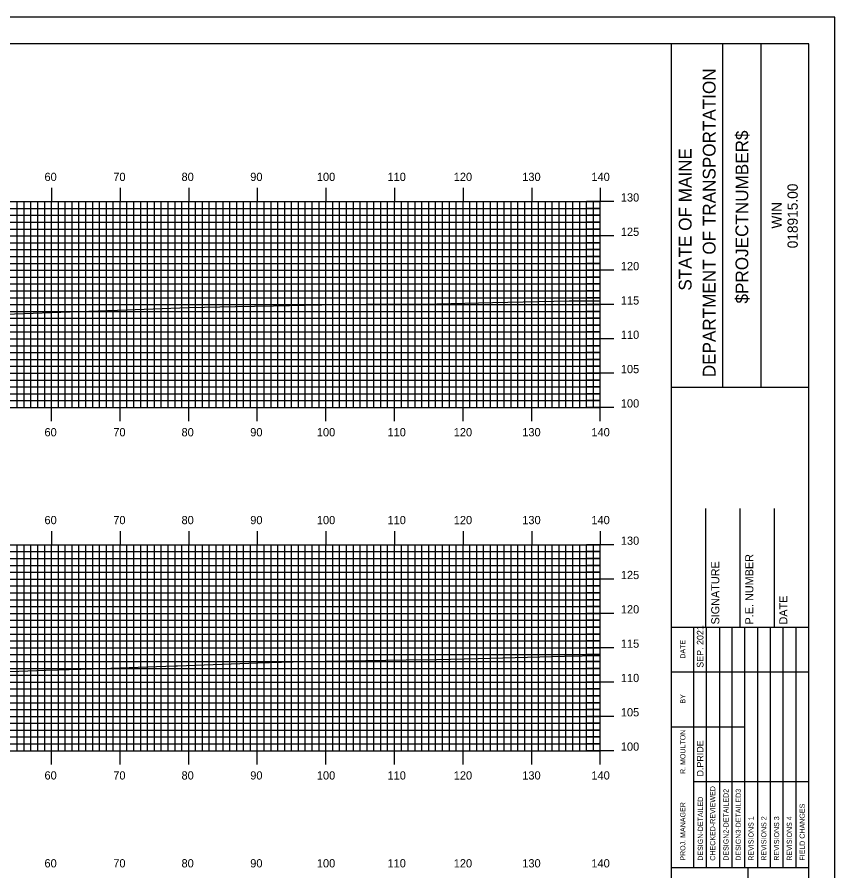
# Model space of a CAD drawing. Extents: x 1788156 to 1788500, y 442591 to 442811.
# Drawn here: x 1788377.1 to 1788496.3, y 442686.2 to 442810.5 of the extents above; entities that cross this region are included whole.
import ezdxf

# ---------------------------------------------------------------- set-up
doc = ezdxf.new("R2010")
doc.units = 0
for name, color, linetype in [('BORDER', 7, 'Continuous'), ('H_V ANNOTATION', 7, 'Continuous'), ('MAJOR', 7, 'Continuous'), ('MINOR', 7, 'Continuous'), ('PLOT BOUNDARY', 7, 'Continuous'), ('S_Roadway_Centerline', 7, 'Continuous')]:
    doc.layers.add(name, color=color, linetype=linetype)

msp = doc.modelspace()

# ---------------------------------------------------------------- linework, layer by layer
at = {"layer": 'BORDER'}
for p, q in [((1788472.53, 442596.67), (1788472.53, 442806.67)), ((1788479.99, 442756.66), (1788479.99, 442806.66)), ((1788485.58, 442756.66), (1788485.58, 442806.66)), ((1788472.53, 442756.65), (1788492.53, 442756.65)), ((1788477.53, 442721.67), (1788477.53, 442738.97)), ((1788482.53, 442721.67), (1788482.53, 442738.97)), ((1788487.53, 442721.67), (1788487.53, 442738.97)), ((1788472.53, 442721.67), (1788492.53, 442721.67)), ((1788472.53, 442686.67), (1788492.53, 442686.67)), ((1788483.71, 442616.67), (1788483.71, 442686.67))]:
    msp.add_line(p, q, dxfattribs=at)
msp.add_lwpolyline([(1788172.53, 442596.67), (1788492.53, 442596.67), (1788492.53, 442806.67), (1788172.53, 442806.67)], close=True, dxfattribs=at)
for points in [[(1788475.76, 442715.17), (1788475.76, 442721.67)], [(1788477.63, 442686.68), (1788477.63, 442721.67)], [(1788479.49, 442721.67), (1788479.49, 442686.68)], [(1788481.35, 442686.68), (1788481.35, 442721.67)], [(1788483.22, 442686.68), (1788483.22, 442721.67)], [(1788485.08, 442686.68), (1788485.08, 442721.67)], [(1788486.94, 442686.68), (1788486.94, 442721.67)], [(1788488.81, 442686.68), (1788488.81, 442721.67)], [(1788490.67, 442686.68), (1788490.67, 442721.67)], [(1788475.76, 442686.68), (1788475.76, 442720.26)], [(1788472.53, 442715.17), (1788492.53, 442715.17)], [(1788472.53, 442707.17), (1788475.76, 442707.17)], [(1788475.76, 442707.17), (1788483.21, 442707.17)], [(1788475.76, 442699.17), (1788492.53, 442699.17)]]:
    msp.add_lwpolyline(points, dxfattribs=at)
at = {"layer": 'MAJOR'}
for p, q in [((1788382.13, 442785.67), (1788382.13, 442783.67)), ((1788392.13, 442785.67), (1788392.13, 442783.67)), ((1788402.13, 442785.67), (1788402.13, 442783.67)), ((1788412.13, 442785.67), (1788412.13, 442783.67)), ((1788422.13, 442785.67), (1788422.13, 442783.67)), ((1788432.13, 442785.67), (1788432.13, 442783.67)), ((1788442.13, 442785.67), (1788442.13, 442783.67)), ((1788452.13, 442785.67), (1788452.13, 442783.67)), ((1788462.13, 442785.67), (1788462.13, 442783.67)), ((1788182.13, 442783.67), (1788462.13, 442783.67)), ((1788182.13, 442783.67), (1788462.13, 442783.67)), ((1788382.13, 442753.67), (1788382.13, 442783.67)), ((1788392.13, 442753.67), (1788392.13, 442783.67)), ((1788402.13, 442753.67), (1788402.13, 442783.67)), ((1788412.13, 442753.67), (1788412.13, 442783.67)), ((1788422.13, 442753.67), (1788422.13, 442783.67)), ((1788432.13, 442753.67), (1788432.13, 442783.67)), ((1788442.13, 442753.67), (1788442.13, 442783.67)), ((1788452.13, 442753.67), (1788452.13, 442783.67)), ((1788464.13, 442783.67), (1788460.13, 442783.67)), ((1788462.13, 442753.67), (1788462.13, 442783.67)), ((1788462.13, 442753.67), (1788462.13, 442783.67)), ((1788182.13, 442778.67), (1788462.13, 442778.67)), ((1788464.13, 442778.67), (1788460.13, 442778.67)), ((1788182.13, 442773.67), (1788462.13, 442773.67)), ((1788464.13, 442773.67), (1788460.13, 442773.67)), ((1788182.13, 442768.67), (1788462.13, 442768.67)), ((1788464.13, 442768.67), (1788460.13, 442768.67)), ((1788182.13, 442763.67), (1788462.13, 442763.67)), ((1788464.13, 442763.67), (1788460.13, 442763.67)), ((1788182.13, 442758.67), (1788462.13, 442758.67)), ((1788464.13, 442758.67), (1788460.13, 442758.67)), ((1788182.13, 442753.67), (1788462.13, 442753.67)), ((1788182.13, 442753.67), (1788462.13, 442753.67)), ((1788382.13, 442751.66), (1788382.13, 442753.67)), ((1788392.13, 442751.66), (1788392.13, 442753.67)), ((1788402.13, 442751.66), (1788402.13, 442753.67)), ((1788412.13, 442751.66), (1788412.13, 442753.67)), ((1788422.13, 442751.66), (1788422.13, 442753.67)), ((1788432.13, 442751.66), (1788432.13, 442753.67)), ((1788442.13, 442751.66), (1788442.13, 442753.67)), ((1788452.13, 442751.66), (1788452.13, 442753.67)), ((1788464.13, 442753.67), (1788460.13, 442753.67)), ((1788462.13, 442751.66), (1788462.13, 442753.67)), ((1788382.13, 442735.67), (1788382.13, 442733.67)), ((1788392.13, 442735.67), (1788392.13, 442733.67)), ((1788402.13, 442735.67), (1788402.13, 442733.67)), ((1788412.13, 442735.67), (1788412.13, 442733.67)), ((1788422.13, 442735.67), (1788422.13, 442733.67)), ((1788432.13, 442735.67), (1788432.13, 442733.67)), ((1788442.13, 442735.67), (1788442.13, 442733.67)), ((1788452.13, 442735.67), (1788452.13, 442733.67)), ((1788462.13, 442735.67), (1788462.13, 442733.67)), ((1788182.13, 442733.67), (1788462.13, 442733.67)), ((1788182.13, 442733.67), (1788462.13, 442733.67)), ((1788382.13, 442703.67), (1788382.13, 442733.67)), ((1788392.13, 442703.67), (1788392.13, 442733.67)), ((1788402.13, 442703.67), (1788402.13, 442733.67)), ((1788412.13, 442703.67), (1788412.13, 442733.67)), ((1788422.13, 442703.67), (1788422.13, 442733.67)), ((1788432.13, 442703.67), (1788432.13, 442733.67)), ((1788442.13, 442703.67), (1788442.13, 442733.67)), ((1788452.13, 442703.67), (1788452.13, 442733.67)), ((1788464.13, 442733.67), (1788460.13, 442733.67)), ((1788462.13, 442703.67), (1788462.13, 442733.67)), ((1788462.13, 442703.67), (1788462.13, 442733.67)), ((1788182.13, 442728.67), (1788462.13, 442728.67)), ((1788464.13, 442728.67), (1788460.13, 442728.67)), ((1788182.13, 442723.67), (1788462.13, 442723.67)), ((1788464.13, 442723.67), (1788460.13, 442723.67)), ((1788182.13, 442718.67), (1788462.13, 442718.67)), ((1788464.13, 442718.67), (1788460.13, 442718.67)), ((1788182.13, 442713.67), (1788462.13, 442713.67)), ((1788464.13, 442713.67), (1788460.13, 442713.67)), ((1788182.13, 442708.67), (1788462.13, 442708.67)), ((1788464.13, 442708.67), (1788460.13, 442708.67)), ((1788182.13, 442703.67), (1788462.13, 442703.67)), ((1788182.13, 442703.67), (1788462.13, 442703.67)), ((1788382.13, 442701.66), (1788382.13, 442703.67)), ((1788392.13, 442701.66), (1788392.13, 442703.67)), ((1788402.13, 442701.66), (1788402.13, 442703.67)), ((1788412.13, 442701.66), (1788412.13, 442703.67)), ((1788422.13, 442701.66), (1788422.13, 442703.67)), ((1788432.13, 442701.66), (1788432.13, 442703.67)), ((1788442.13, 442701.66), (1788442.13, 442703.67)), ((1788452.13, 442701.66), (1788452.13, 442703.67)), ((1788464.13, 442703.67), (1788460.13, 442703.67)), ((1788462.13, 442701.66), (1788462.13, 442703.67))]:
    msp.add_line(p, q, dxfattribs=at)
at = {"layer": 'MINOR'}
for p, q in [((1788377.13, 442753.67), (1788377.13, 442783.67)), ((1788378.13, 442753.67), (1788378.13, 442783.67)), ((1788379.13, 442753.67), (1788379.13, 442783.67)), ((1788380.13, 442753.67), (1788380.13, 442783.67)), ((1788381.13, 442753.67), (1788381.13, 442783.67)), ((1788383.13, 442753.67), (1788383.13, 442783.67)), ((1788384.13, 442753.67), (1788384.13, 442783.67)), ((1788385.13, 442753.67), (1788385.13, 442783.67)), ((1788386.13, 442753.67), (1788386.13, 442783.67)), ((1788387.13, 442753.67), (1788387.13, 442783.67)), ((1788388.13, 442753.67), (1788388.13, 442783.67)), ((1788389.13, 442753.67), (1788389.13, 442783.67)), ((1788390.13, 442753.67), (1788390.13, 442783.67)), ((1788391.13, 442753.67), (1788391.13, 442783.67)), ((1788393.13, 442753.67), (1788393.13, 442783.67)), ((1788394.13, 442753.67), (1788394.13, 442783.67)), ((1788395.13, 442753.67), (1788395.13, 442783.67)), ((1788396.13, 442753.67), (1788396.13, 442783.67)), ((1788397.13, 442753.67), (1788397.13, 442783.67)), ((1788398.13, 442753.67), (1788398.13, 442783.67)), ((1788399.13, 442753.67), (1788399.13, 442783.67)), ((1788400.13, 442753.67), (1788400.13, 442783.67)), ((1788401.13, 442753.67), (1788401.13, 442783.67)), ((1788403.13, 442753.67), (1788403.13, 442783.67)), ((1788404.13, 442753.67), (1788404.13, 442783.67)), ((1788405.13, 442753.67), (1788405.13, 442783.67)), ((1788406.13, 442753.67), (1788406.13, 442783.67)), ((1788407.13, 442753.67), (1788407.13, 442783.67)), ((1788408.13, 442753.67), (1788408.13, 442783.67)), ((1788409.13, 442753.67), (1788409.13, 442783.67)), ((1788410.13, 442753.67), (1788410.13, 442783.67)), ((1788411.13, 442753.67), (1788411.13, 442783.67)), ((1788413.13, 442753.67), (1788413.13, 442783.67)), ((1788414.13, 442753.67), (1788414.13, 442783.67)), ((1788415.13, 442753.67), (1788415.13, 442783.67)), ((1788416.13, 442753.67), (1788416.13, 442783.67)), ((1788417.13, 442753.67), (1788417.13, 442783.67)), ((1788418.13, 442753.67), (1788418.13, 442783.67)), ((1788419.13, 442753.67), (1788419.13, 442783.67)), ((1788420.13, 442753.67), (1788420.13, 442783.67)), ((1788421.13, 442753.67), (1788421.13, 442783.67)), ((1788423.13, 442753.67), (1788423.13, 442783.67)), ((1788424.13, 442753.67), (1788424.13, 442783.67)), ((1788425.13, 442753.67), (1788425.13, 442783.67)), ((1788426.13, 442753.67), (1788426.13, 442783.67)), ((1788427.13, 442753.67), (1788427.13, 442783.67)), ((1788428.13, 442753.67), (1788428.13, 442783.67)), ((1788429.13, 442753.67), (1788429.13, 442783.67)), ((1788430.13, 442753.67), (1788430.13, 442783.67)), ((1788431.13, 442753.67), (1788431.13, 442783.67)), ((1788433.13, 442753.67), (1788433.13, 442783.67)), ((1788434.13, 442753.67), (1788434.13, 442783.67)), ((1788435.13, 442753.67), (1788435.13, 442783.67)), ((1788436.13, 442753.67), (1788436.13, 442783.67)), ((1788437.13, 442753.67), (1788437.13, 442783.67)), ((1788438.13, 442753.67), (1788438.13, 442783.67)), ((1788439.13, 442753.67), (1788439.13, 442783.67)), ((1788440.13, 442753.67), (1788440.13, 442783.67)), ((1788441.13, 442753.67), (1788441.13, 442783.67)), ((1788443.13, 442753.67), (1788443.13, 442783.67)), ((1788444.13, 442753.67), (1788444.13, 442783.67)), ((1788445.13, 442753.67), (1788445.13, 442783.67)), ((1788446.13, 442753.67), (1788446.13, 442783.67)), ((1788447.13, 442753.67), (1788447.13, 442783.67)), ((1788448.13, 442753.67), (1788448.13, 442783.67)), ((1788449.13, 442753.67), (1788449.13, 442783.67)), ((1788450.13, 442753.67), (1788450.13, 442783.67)), ((1788451.13, 442753.67), (1788451.13, 442783.67)), ((1788453.13, 442753.67), (1788453.13, 442783.67)), ((1788454.13, 442753.67), (1788454.13, 442783.67)), ((1788455.13, 442753.67), (1788455.13, 442783.67)), ((1788456.13, 442753.67), (1788456.13, 442783.67)), ((1788457.13, 442753.67), (1788457.13, 442783.67)), ((1788458.13, 442753.67), (1788458.13, 442783.67)), ((1788459.13, 442753.67), (1788459.13, 442783.67)), ((1788460.13, 442753.67), (1788460.13, 442783.67)), ((1788461.13, 442753.67), (1788461.13, 442783.67)), ((1788182.13, 442782.67), (1788462.13, 442782.67)), ((1788462.13, 442782.67), (1788460.13, 442782.67)), ((1788182.13, 442781.67), (1788462.13, 442781.67)), ((1788462.13, 442781.67), (1788460.13, 442781.67)), ((1788182.13, 442780.67), (1788462.13, 442780.67)), ((1788462.13, 442780.67), (1788460.13, 442780.67)), ((1788182.13, 442779.67), (1788462.13, 442779.67)), ((1788462.13, 442779.67), (1788460.13, 442779.67)), ((1788182.13, 442777.67), (1788462.13, 442777.67)), ((1788462.13, 442777.67), (1788460.13, 442777.67)), ((1788182.13, 442776.67), (1788462.13, 442776.67)), ((1788462.13, 442776.67), (1788460.13, 442776.67)), ((1788182.13, 442775.67), (1788462.13, 442775.67)), ((1788462.13, 442775.67), (1788460.13, 442775.67)), ((1788182.13, 442774.67), (1788462.13, 442774.67)), ((1788462.13, 442774.67), (1788460.13, 442774.67)), ((1788182.13, 442772.67), (1788462.13, 442772.67)), ((1788462.13, 442772.67), (1788460.13, 442772.67)), ((1788182.13, 442771.67), (1788462.13, 442771.67)), ((1788462.13, 442771.67), (1788460.13, 442771.67)), ((1788182.13, 442770.67), (1788462.13, 442770.67)), ((1788462.13, 442770.67), (1788460.13, 442770.67)), ((1788182.13, 442769.67), (1788462.13, 442769.67)), ((1788462.13, 442769.67), (1788460.13, 442769.67)), ((1788182.13, 442767.67), (1788462.13, 442767.67)), ((1788462.13, 442767.67), (1788460.13, 442767.67)), ((1788182.13, 442766.67), (1788462.13, 442766.67)), ((1788462.13, 442766.67), (1788460.13, 442766.67)), ((1788182.13, 442765.67), (1788462.13, 442765.67)), ((1788462.13, 442765.67), (1788460.13, 442765.67)), ((1788182.13, 442764.67), (1788462.13, 442764.67)), ((1788462.13, 442764.67), (1788460.13, 442764.67)), ((1788182.13, 442762.67), (1788462.13, 442762.67)), ((1788462.13, 442762.67), (1788460.13, 442762.67)), ((1788182.13, 442761.67), (1788462.13, 442761.67)), ((1788462.13, 442761.67), (1788460.13, 442761.67)), ((1788182.13, 442760.67), (1788462.13, 442760.67)), ((1788462.13, 442760.67), (1788460.13, 442760.67)), ((1788182.13, 442759.67), (1788462.13, 442759.67)), ((1788462.13, 442759.67), (1788460.13, 442759.67)), ((1788182.13, 442757.67), (1788462.13, 442757.67)), ((1788462.13, 442757.67), (1788460.13, 442757.67)), ((1788182.13, 442756.67), (1788462.13, 442756.67)), ((1788462.13, 442756.67), (1788460.13, 442756.67)), ((1788182.13, 442755.67), (1788462.13, 442755.67)), ((1788462.13, 442755.67), (1788460.13, 442755.67)), ((1788182.13, 442754.67), (1788462.13, 442754.67)), ((1788462.13, 442754.67), (1788460.13, 442754.67)), ((1788182.13, 442732.67), (1788462.13, 442732.67)), ((1788377.13, 442703.67), (1788377.13, 442733.67)), ((1788378.13, 442703.67), (1788378.13, 442733.67)), ((1788379.13, 442703.67), (1788379.13, 442733.67)), ((1788380.13, 442703.67), (1788380.13, 442733.67)), ((1788381.13, 442703.67), (1788381.13, 442733.67)), ((1788383.13, 442703.67), (1788383.13, 442733.67)), ((1788384.13, 442703.67), (1788384.13, 442733.67)), ((1788385.13, 442703.67), (1788385.13, 442733.67)), ((1788386.13, 442703.67), (1788386.13, 442733.67)), ((1788387.13, 442703.67), (1788387.13, 442733.67)), ((1788388.13, 442703.67), (1788388.13, 442733.67)), ((1788389.13, 442703.67), (1788389.13, 442733.67)), ((1788390.13, 442703.67), (1788390.13, 442733.67)), ((1788391.13, 442703.67), (1788391.13, 442733.67)), ((1788393.13, 442703.67), (1788393.13, 442733.67)), ((1788394.13, 442703.67), (1788394.13, 442733.67)), ((1788395.13, 442703.67), (1788395.13, 442733.67)), ((1788396.13, 442703.67), (1788396.13, 442733.67)), ((1788397.13, 442703.67), (1788397.13, 442733.67)), ((1788398.13, 442703.67), (1788398.13, 442733.67)), ((1788399.13, 442703.67), (1788399.13, 442733.67)), ((1788400.13, 442703.67), (1788400.13, 442733.67)), ((1788401.13, 442703.67), (1788401.13, 442733.67)), ((1788403.13, 442703.67), (1788403.13, 442733.67)), ((1788404.13, 442703.67), (1788404.13, 442733.67)), ((1788405.13, 442703.67), (1788405.13, 442733.67)), ((1788406.13, 442703.67), (1788406.13, 442733.67)), ((1788407.13, 442703.67), (1788407.13, 442733.67)), ((1788408.13, 442703.67), (1788408.13, 442733.67)), ((1788409.13, 442703.67), (1788409.13, 442733.67)), ((1788410.13, 442703.67), (1788410.13, 442733.67)), ((1788411.13, 442703.67), (1788411.13, 442733.67)), ((1788413.13, 442703.67), (1788413.13, 442733.67)), ((1788414.13, 442703.67), (1788414.13, 442733.67)), ((1788415.13, 442703.67), (1788415.13, 442733.67)), ((1788416.13, 442703.67), (1788416.13, 442733.67)), ((1788417.13, 442703.67), (1788417.13, 442733.67)), ((1788418.13, 442703.67), (1788418.13, 442733.67)), ((1788419.13, 442703.67), (1788419.13, 442733.67)), ((1788420.13, 442703.67), (1788420.13, 442733.67)), ((1788421.13, 442703.67), (1788421.13, 442733.67)), ((1788423.13, 442703.67), (1788423.13, 442733.67)), ((1788424.13, 442703.67), (1788424.13, 442733.67)), ((1788425.13, 442703.67), (1788425.13, 442733.67)), ((1788426.13, 442703.67), (1788426.13, 442733.67)), ((1788427.13, 442703.67), (1788427.13, 442733.67)), ((1788428.13, 442703.67), (1788428.13, 442733.67)), ((1788429.13, 442703.67), (1788429.13, 442733.67)), ((1788430.13, 442703.67), (1788430.13, 442733.67)), ((1788431.13, 442703.67), (1788431.13, 442733.67)), ((1788433.13, 442703.67), (1788433.13, 442733.67)), ((1788434.13, 442703.67), (1788434.13, 442733.67)), ((1788435.13, 442703.67), (1788435.13, 442733.67)), ((1788436.13, 442703.67), (1788436.13, 442733.67)), ((1788437.13, 442703.67), (1788437.13, 442733.67)), ((1788438.13, 442703.67), (1788438.13, 442733.67)), ((1788439.13, 442703.67), (1788439.13, 442733.67)), ((1788440.13, 442703.67), (1788440.13, 442733.67)), ((1788441.13, 442703.67), (1788441.13, 442733.67)), ((1788443.13, 442703.67), (1788443.13, 442733.67)), ((1788444.13, 442703.67), (1788444.13, 442733.67)), ((1788445.13, 442703.67), (1788445.13, 442733.67)), ((1788446.13, 442703.67), (1788446.13, 442733.67)), ((1788447.13, 442703.67), (1788447.13, 442733.67)), ((1788448.13, 442703.67), (1788448.13, 442733.67)), ((1788449.13, 442703.67), (1788449.13, 442733.67)), ((1788450.13, 442703.67), (1788450.13, 442733.67)), ((1788451.13, 442703.67), (1788451.13, 442733.67)), ((1788453.13, 442703.67), (1788453.13, 442733.67)), ((1788454.13, 442703.67), (1788454.13, 442733.67)), ((1788455.13, 442703.67), (1788455.13, 442733.67)), ((1788456.13, 442703.67), (1788456.13, 442733.67)), ((1788457.13, 442703.67), (1788457.13, 442733.67)), ((1788458.13, 442703.67), (1788458.13, 442733.67)), ((1788459.13, 442703.67), (1788459.13, 442733.67)), ((1788460.13, 442703.67), (1788460.13, 442733.67)), ((1788462.13, 442732.67), (1788460.13, 442732.67)), ((1788461.13, 442703.67), (1788461.13, 442733.67)), ((1788182.13, 442731.67), (1788462.13, 442731.67)), ((1788462.13, 442731.67), (1788460.13, 442731.67)), ((1788182.13, 442730.67), (1788462.13, 442730.67)), ((1788462.13, 442730.67), (1788460.13, 442730.67)), ((1788182.13, 442729.67), (1788462.13, 442729.67)), ((1788462.13, 442729.67), (1788460.13, 442729.67)), ((1788182.13, 442727.67), (1788462.13, 442727.67)), ((1788462.13, 442727.67), (1788460.13, 442727.67)), ((1788182.13, 442726.67), (1788462.13, 442726.67)), ((1788462.13, 442726.67), (1788460.13, 442726.67)), ((1788182.13, 442725.67), (1788462.13, 442725.67)), ((1788462.13, 442725.67), (1788460.13, 442725.67)), ((1788182.13, 442724.67), (1788462.13, 442724.67)), ((1788462.13, 442724.67), (1788460.13, 442724.67)), ((1788182.13, 442722.67), (1788462.13, 442722.67)), ((1788462.13, 442722.67), (1788460.13, 442722.67)), ((1788182.13, 442721.67), (1788462.13, 442721.67)), ((1788462.13, 442721.67), (1788460.13, 442721.67)), ((1788182.13, 442720.67), (1788462.13, 442720.67)), ((1788462.13, 442720.67), (1788460.13, 442720.67)), ((1788182.13, 442719.67), (1788462.13, 442719.67)), ((1788462.13, 442719.67), (1788460.13, 442719.67)), ((1788182.13, 442717.67), (1788462.13, 442717.67)), ((1788462.13, 442717.67), (1788460.13, 442717.67)), ((1788182.13, 442716.67), (1788462.13, 442716.67)), ((1788462.13, 442716.67), (1788460.13, 442716.67)), ((1788182.13, 442715.67), (1788462.13, 442715.67)), ((1788462.13, 442715.67), (1788460.13, 442715.67)), ((1788182.13, 442714.67), (1788462.13, 442714.67)), ((1788462.13, 442714.67), (1788460.13, 442714.67)), ((1788182.13, 442712.67), (1788462.13, 442712.67)), ((1788462.13, 442712.67), (1788460.13, 442712.67)), ((1788182.13, 442711.67), (1788462.13, 442711.67)), ((1788462.13, 442711.67), (1788460.13, 442711.67)), ((1788182.13, 442710.67), (1788462.13, 442710.67)), ((1788462.13, 442710.67), (1788460.13, 442710.67)), ((1788182.13, 442709.67), (1788462.13, 442709.67)), ((1788462.13, 442709.67), (1788460.13, 442709.67)), ((1788182.13, 442707.67), (1788462.13, 442707.67)), ((1788182.13, 442706.67), (1788462.13, 442706.67)), ((1788462.13, 442707.67), (1788460.13, 442707.67)), ((1788462.13, 442706.67), (1788460.13, 442706.67)), ((1788182.13, 442705.67), (1788462.13, 442705.67)), ((1788462.13, 442705.67), (1788460.13, 442705.67)), ((1788182.13, 442704.67), (1788462.13, 442704.67)), ((1788462.13, 442704.67), (1788460.13, 442704.67))]:
    msp.add_line(p, q, dxfattribs=at)
at = {"layer": 'PLOT BOUNDARY'}
msp.add_lwpolyline([(1788156.34, 442590.55), (1788496.34, 442590.55), (1788496.34, 442810.55), (1788156.34, 442810.55)], close=True, dxfattribs=at)
at = {"layer": 'S_Roadway_Centerline'}
for points in [[(1788371.24, 442767.14), (1788390.29, 442767.78), (1788390.42, 442767.78), (1788402.16, 442768.26), (1788408.95, 442768.39), (1788414.47, 442768.49), (1788423.89, 442768.67), (1788428.02, 442768.73), (1788438.29, 442768.78), (1788446.43, 442768.95), (1788457.6, 442769.19), (1788462.13, 442769.23)], [(1788368.07, 442714.91), (1788381.28, 442715.39), (1788388.11, 442715.58), (1788400.09, 442716.04), (1788400.25, 442716.05), (1788400.5, 442716.06), (1788412.2, 442716.45), (1788419.13, 442716.68), (1788433.85, 442716.89), (1788438.27, 442716.97), (1788444.35, 442717.12), (1788456.91, 442717.43), (1788462.13, 442717.54)]]:
    msp.add_lwpolyline(points, dxfattribs=at)

# ---------------------------------------------------------------- texts
at = {"layer": 'BORDER'}
for s, height, p in [('DEPARTMENT OF TRANSPORTATION', 1.8635, (1788478.94, 442758.08)), ('$PROJECTNUMBER$', 1.8635, (1788483.71, 442768.82)), ('STATE OF MAINE', 1.8635, (1788475.44, 442770.69)), ('018915.00', 1.491, (1788490.92, 442776.86)), ('WIN', 1.491, (1788488.6, 442779.73)), ('P.E. NUMBER', 1.1811, (1788484.45, 442722.06)), ('SIGNATURE', 1.181, (1788479.49, 442722.06)), ('DATE', 1.181, (1788489.41, 442722.06)), ('SEP. 2021', 0.969, (1788477.18, 442715.76)), ('DATE', 0.743, (1788474.54, 442717.08)), ('BY', 0.743, (1788474.54, 442710.54)), ('R. MOULTON', 0.745, (1788474.54, 442700.28)), ('D.PRIDE', 0.969, (1788477.18, 442699.92)), ('CHECKED-REVIEWED', 0.7455, (1788478.89, 442687.65)), ('DESIGN2-DETAILED2', 0.7455, (1788480.83, 442687.65)), ('DESIGN3-DETAILED3', 0.7455, (1788482.62, 442687.65)), ('DESIGN-DETAILED', 0.7455, (1788477.1, 442687.65)), ('PROJ. MANAGER', 0.7455, (1788474.54, 442687.65)), ('FIELD CHANGES', 0.7455, (1788491.94, 442687.65)), ('REVISIONS 1', 0.7455, (1788484.48, 442687.65)), ('REVISIONS 2', 0.7455, (1788486.35, 442687.65)), ('REVISIONS 3', 0.7455, (1788488.21, 442687.65)), ('REVISIONS 4', 0.7455, (1788490.07, 442687.65))]:
    msp.add_text(s, height=height, rotation=90, dxfattribs=at).set_placement(p)
at = {"layer": 'H_V ANNOTATION'}
for s, p in [('60', (1788381.1, 442786.67)), ('70', (1788391.13, 442786.67)), ('80', (1788401.08, 442786.67)), ('90', (1788411.1, 442786.67)), ('100', (1788420.81, 442786.67)), ('110', (1788431.11, 442786.67)), ('120', (1788440.77, 442786.67)), ('130', (1788450.76, 442786.67)), ('140', (1788460.84, 442786.67)), ('130', (1788465.13, 442783.67)), ('125', (1788465.13, 442778.67)), ('120', (1788465.13, 442773.67)), ('115', (1788465.13, 442768.67)), ('110', (1788465.13, 442763.67)), ('105', (1788465.13, 442758.67)), ('100', (1788465.13, 442753.67)), ('60', (1788381.1, 442749.47)), ('70', (1788391.13, 442749.47)), ('80', (1788401.08, 442749.47)), ('90', (1788411.1, 442749.47)), ('100', (1788420.81, 442749.47)), ('110', (1788431.11, 442749.47)), ('120', (1788440.77, 442749.47)), ('130', (1788450.76, 442749.47)), ('140', (1788460.84, 442749.47)), ('60', (1788381.1, 442736.67)), ('70', (1788391.13, 442736.67)), ('80', (1788401.08, 442736.67)), ('90', (1788411.1, 442736.67)), ('100', (1788420.81, 442736.67)), ('110', (1788431.11, 442736.67)), ('120', (1788440.77, 442736.67)), ('130', (1788450.76, 442736.67)), ('140', (1788460.84, 442736.67)), ('130', (1788465.13, 442733.67)), ('125', (1788465.13, 442728.67)), ('120', (1788465.13, 442723.67)), ('115', (1788465.13, 442718.67)), ('110', (1788465.13, 442713.67)), ('105', (1788465.13, 442708.67)), ('100', (1788465.13, 442703.67)), ('60', (1788381.1, 442699.47)), ('70', (1788391.13, 442699.47)), ('80', (1788401.08, 442699.47)), ('90', (1788411.1, 442699.47)), ('100', (1788420.81, 442699.47)), ('110', (1788431.11, 442699.47)), ('120', (1788440.77, 442699.47)), ('130', (1788450.76, 442699.47)), ('140', (1788460.84, 442699.47)), ('60', (1788381.1, 442686.67)), ('70', (1788391.13, 442686.67)), ('80', (1788401.08, 442686.67)), ('90', (1788411.1, 442686.67)), ('100', (1788420.81, 442686.67)), ('110', (1788431.11, 442686.67)), ('120', (1788440.77, 442686.67)), ('130', (1788450.76, 442686.67)), ('140', (1788460.84, 442686.67))]:
    msp.add_text(s, height=1.2, dxfattribs=at).set_placement(p)

doc.saveas('drawing.dxf')
